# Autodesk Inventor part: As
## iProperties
Created: 2007-06
Part Number: As
Material: Steel
Document SubType Name: Modeling
Designer: Phil Trethewie
Author: Phil Trethewie
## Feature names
1. Extrusion1
2. Extrusion2
3. Hole1
4. Mirror1
